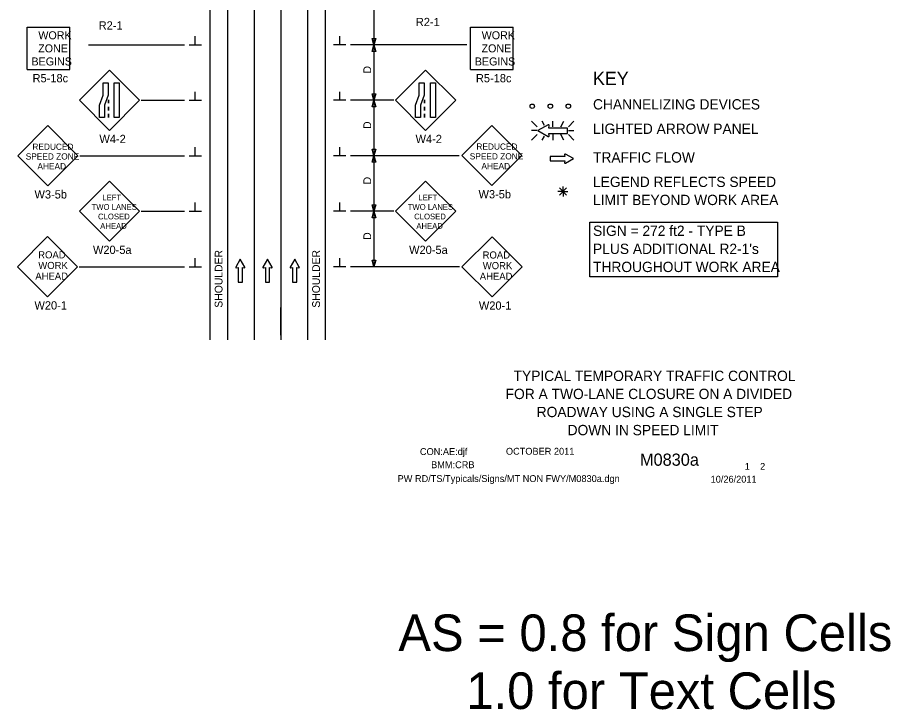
# Model space of a CAD drawing. Extents: x 16727 to 18475, y 5729 to 6909.
# Drawn here: x 16728 to 17515, y 5729 to 6353 of the extents above; entities that cross this region are included whole.
import ezdxf

# ---------------------------------------------------------------- set-up
doc = ezdxf.new("R2010")
doc.units = 0
for name, color, linetype in [('ALI_LEGAL_EX', 7, 'Continuous'), ('BORDER', 7, 'Continuous'), ('BORDER_SIGNAL_WO', 7, 'Continuous'), ('MT_SCRATCH_LEVEL_E', 7, 'Continuous'), ('PAVT_EDGE_EX', 7, 'Continuous'), ('TRAFFIC_SIGNS_PR', 7, 'Continuous'), ('TYPICAL_TEXT_DIMEN_EX', 7, 'Continuous'), ('TYPICAL_TEXT_DIMEN_PR', 7, 'Continuous')]:
    doc.layers.add(name, color=color, linetype=linetype)

msp = doc.modelspace()

# ---------------------------------------------------------------- linework, layer by layer
at = {"layer": 'ALI_LEGAL_EX'}
for p, q in [((16941.23, 6891.16), (16941.23, 6061.98)), ((16965.23, 6891.16), (16965.23, 6061.98)), ((16965.23, 6891.16), (16965.23, 6061.98))]:
    msp.add_line(p, q, dxfattribs=at)
for points in [[(16941.23, 6291.16), (16941.23, 6266.16)], [(16965.23, 6291.16), (16965.23, 6266.16)], [(16941.23, 6191.16), (16941.23, 6166.16)], [(16965.23, 6191.16), (16965.23, 6166.16)], [(16941.23, 6091.16), (16941.23, 6066.16)], [(16965.23, 6066.16), (16965.23, 6091.16)], [(16965.23, 6091.16), (16965.23, 6066.16)]]:
    msp.add_lwpolyline(points, dxfattribs=at)
at = {"layer": 'MT_SCRATCH_LEVEL_E'}
for p, q in [((17221.51, 6227.16), (17208.25, 6227.16)), ((17208.25, 6227.16), (17208.25, 6223.42)), ((17221.51, 6227.16), (17208.25, 6227.16)), ((17208.25, 6227.16), (17208.25, 6223.42)), ((17208.25, 6223.42), (17221.51, 6223.42)), ((17208.25, 6223.42), (17221.51, 6223.42)), ((17221.19, 6228.94), (17221.51, 6227.16)), ((17221.19, 6228.94), (17221.51, 6227.16)), ((17221.51, 6223.42), (17221.19, 6221.64)), ((17221.51, 6223.42), (17221.19, 6221.64)), ((17229.12, 6225.31), (17221.88, 6229.42)), ((17229.12, 6225.31), (17221.88, 6229.42)), ((17221.88, 6221.16), (17229.12, 6225.31)), ((17221.88, 6221.16), (17229.12, 6225.31)), ((16928.67, 6134.8), (16924.56, 6127.56)), ((16928.67, 6134.8), (16924.56, 6127.56)), ((16932.82, 6127.56), (16928.67, 6134.8)), ((16932.82, 6127.56), (16928.67, 6134.8)), ((16953.2, 6134.8), (16949.09, 6127.56)), ((16953.2, 6134.8), (16949.09, 6127.56)), ((16957.35, 6127.56), (16953.2, 6134.8)), ((16957.35, 6127.56), (16953.2, 6134.8)), ((16977.76, 6134.8), (16973.65, 6127.56)), ((16977.76, 6134.8), (16973.65, 6127.56)), ((16981.9, 6127.56), (16977.76, 6134.8)), ((16981.9, 6127.56), (16977.76, 6134.8)), ((16925.04, 6126.88), (16926.82, 6127.19)), ((16925.04, 6126.88), (16926.82, 6127.19)), ((16926.82, 6127.19), (16926.82, 6113.93)), ((16926.82, 6127.19), (16926.82, 6113.93)), ((16930.56, 6113.93), (16930.56, 6127.19)), ((16930.56, 6127.19), (16932.34, 6126.88)), ((16930.56, 6113.93), (16930.56, 6127.19)), ((16930.56, 6127.19), (16932.34, 6126.88)), ((16949.57, 6126.88), (16951.35, 6127.19)), ((16949.57, 6126.88), (16951.35, 6127.19)), ((16951.35, 6127.19), (16951.35, 6113.93)), ((16951.35, 6127.19), (16951.35, 6113.93)), ((16955.09, 6113.93), (16955.09, 6127.19)), ((16955.09, 6127.19), (16956.87, 6126.88)), ((16955.09, 6113.93), (16955.09, 6127.19)), ((16955.09, 6127.19), (16956.87, 6126.88)), ((16974.13, 6126.88), (16975.9, 6127.19)), ((16974.13, 6126.88), (16975.9, 6127.19)), ((16975.9, 6127.19), (16975.9, 6113.93)), ((16975.9, 6127.19), (16975.9, 6113.93)), ((16979.65, 6113.93), (16979.65, 6127.19)), ((16979.65, 6127.19), (16981.42, 6126.88)), ((16979.65, 6113.93), (16979.65, 6127.19)), ((16979.65, 6127.19), (16981.42, 6126.88)), ((16926.82, 6113.93), (16930.56, 6113.93)), ((16926.82, 6113.93), (16930.56, 6113.93)), ((16951.35, 6113.93), (16955.09, 6113.93)), ((16951.35, 6113.93), (16955.09, 6113.93)), ((16975.9, 6113.93), (16979.65, 6113.93)), ((16975.9, 6113.93), (16979.65, 6113.93))]:
    msp.add_line(p, q, dxfattribs=at)
for centre, start, end in [((17221.65, 6229.01), 60.42484, 189.96381), ((17221.65, 6229.01), 60.42484, 189.96381), ((17221.65, 6221.57), 170.03619, 299.77312), ((17221.65, 6221.57), 170.03619, 299.77312), ((16924.97, 6127.33), 150.42484, 279.96381), ((16924.97, 6127.33), 150.42484, 279.96381), ((16932.41, 6127.34), 260.03619, 29.77312), ((16932.41, 6127.34), 260.03619, 29.77312), ((16949.49, 6127.33), 150.42484, 279.96381), ((16949.49, 6127.33), 150.42484, 279.96381), ((16956.94, 6127.34), 260.03619, 29.77312), ((16956.94, 6127.34), 260.03619, 29.77312), ((16974.05, 6127.33), 150.42484, 279.96381), ((16974.05, 6127.33), 150.42484, 279.96381), ((16981.49, 6127.34), 260.03619, 29.77312), ((16981.49, 6127.34), 260.03619, 29.77312)]:
    msp.add_arc(centre, 0.463, start, end, dxfattribs=at)
at = {"layer": 'PAVT_EDGE_EX'}
for p, q in [((16901.23, 6891.16), (16901.23, 6061.98)), ((16917.23, 6891.16), (16917.23, 6061.98)), ((16917.23, 6891.16), (16917.23, 6061.98)), ((16989.23, 6891.16), (16989.23, 6061.98)), ((17005.23, 6891.16), (17005.23, 6061.98))]:
    msp.add_line(p, q, dxfattribs=at)
at = {"layer": 'TRAFFIC_SIGNS_PR'}
for p, q in [((16736.49, 6305.58), (16736.49, 6343.98)), ((16736.49, 6343.98), (16774.89, 6343.98)), ((16774.89, 6305.58), (16774.89, 6343.98)), ((17136.41, 6305.58), (17136.41, 6343.98)), ((17136.41, 6343.98), (17174.81, 6343.98)), ((17174.81, 6305.58), (17174.81, 6343.98)), ((16736.49, 6305.58), (16774.89, 6305.58)), ((16810.64, 6305.09), (16783.48, 6277.93)), ((16837.79, 6277.93), (16810.64, 6305.09)), ((17095.82, 6305.09), (17068.67, 6277.93)), ((17122.98, 6277.93), (17095.82, 6305.09)), ((17136.41, 6305.58), (17174.81, 6305.58)), ((16783.48, 6277.93), (16810.64, 6250.78)), ((16809.39, 6278.43), (16809.39, 6275.23)), ((16809.79, 6278.43), (16809.79, 6275.23)), ((16810.64, 6250.78), (16837.79, 6277.93)), ((17068.67, 6277.93), (17095.82, 6250.78)), ((17094.58, 6278.43), (17094.58, 6275.23)), ((17094.98, 6278.43), (17094.98, 6275.23)), ((17095.82, 6250.78), (17122.98, 6277.93)), ((16809.39, 6272.03), (16809.39, 6268.83)), ((16809.79, 6272.03), (16809.79, 6268.83)), ((17094.58, 6272.03), (17094.58, 6268.83)), ((17094.98, 6272.03), (17094.98, 6268.83)), ((16809.39, 6265.63), (16809.39, 6262.43)), ((16809.79, 6265.63), (16809.79, 6262.43)), ((17094.58, 6265.63), (17094.58, 6262.43)), ((17094.98, 6265.63), (17094.98, 6262.43)), ((16755.08, 6255.12), (16727.92, 6227.97)), ((16782.23, 6227.97), (16755.08, 6255.12)), ((17155.62, 6255.25), (17128.47, 6228.1)), ((17182.77, 6228.1), (17155.62, 6255.25)), ((17191.46, 6259.03), (17196.39, 6254.1)), ((17203.22, 6255.21), (17201.01, 6259.03)), ((17210.54, 6254.1), (17210.54, 6259.03)), ((17217.78, 6254.1), (17220.62, 6259.03)), ((17224.69, 6254.1), (17229.63, 6259.04)), ((17196.39, 6250.54), (17191.46, 6250.54)), ((17191.46, 6242.06), (17196.39, 6246.99)), ((17200.97, 6242.05), (17203.08, 6245.72)), ((17210.54, 6246.99), (17210.54, 6242.05)), ((17220.67, 6242.05), (17217.82, 6246.99)), ((17224.69, 6250.54), (17229.63, 6250.54)), ((17224.69, 6246.99), (17229.63, 6242.05)), ((16727.92, 6227.97), (16755.08, 6200.81)), ((16755.08, 6200.81), (16782.23, 6227.97)), ((17128.47, 6228.1), (17155.62, 6200.94)), ((17155.62, 6200.94), (17182.77, 6228.1)), ((16810.64, 6205.1), (16783.48, 6177.95)), ((16837.79, 6177.95), (16810.64, 6205.1)), ((17095.82, 6205.1), (17068.67, 6177.95)), ((17122.98, 6177.95), (17095.82, 6205.1)), ((16783.48, 6177.95), (16810.64, 6150.8)), ((16810.64, 6150.8), (16837.79, 6177.95)), ((17068.67, 6177.95), (17095.82, 6150.8)), ((17095.82, 6150.8), (17122.98, 6177.95)), ((16754.82, 6155.02), (16727.66, 6127.86)), ((16781.97, 6127.86), (16754.82, 6155.02)), ((17155.73, 6154.86), (17128.57, 6127.71)), ((17182.88, 6127.71), (17155.73, 6154.86)), ((16727.66, 6127.86), (16754.82, 6100.71)), ((16754.82, 6100.71), (16781.97, 6127.86)), ((17128.57, 6127.71), (17155.73, 6100.55)), ((17155.73, 6100.55), (17182.88, 6127.71))]:
    msp.add_line(p, q, dxfattribs=at)
for points in [[(16809.39, 6293.67), (16809.39, 6282.49), (16806.04, 6273.61), (16806.04, 6262.43), (16801.55, 6262.43), (16801.55, 6273.61), (16804.9, 6282.49), (16804.9, 6293.67)], [(16819.52, 6293.67), (16819.52, 6262.43), (16815.03, 6262.43), (16815.03, 6293.67)], [(17094.58, 6293.67), (17094.58, 6282.49), (17091.23, 6273.61), (17091.23, 6262.43), (17086.74, 6262.43), (17086.74, 6273.61), (17090.08, 6282.49), (17090.08, 6293.67)], [(17104.71, 6293.67), (17104.71, 6262.43), (17100.22, 6262.43), (17100.22, 6293.67)]]:
    msp.add_lwpolyline(points, close=True, dxfattribs=at)
for points in [[(17206.47, 6255.82), (17197.18, 6250.54), (17206.47, 6245.22)], [(17207.34, 6245.85), (17206.94, 6248.12), (17223.96, 6248.12), (17223.96, 6252.92), (17206.94, 6252.92), (17207.35, 6255.2)]]:
    msp.add_lwpolyline(points, dxfattribs=at)
for centre in [(17192.02, 6272.58), (17208.32, 6272.58), (17224.62, 6272.58)]:
    msp.add_circle(centre, 2, dxfattribs=at)
for centre, radius, start, end in [((17206.76, 6255.3), 0.598, 350.73078, 118.89165), ((17206.76, 6245.75), 0.597, 241.48329, 9.95933)]:
    msp.add_arc(centre, radius, start, end, dxfattribs=at)
at = {"layer": 'TYPICAL_TEXT_DIMEN_EX'}
msp.add_lwpolyline([(17243.85, 6168.04), (17413.3, 6168.04), (17413.3, 6118.85), (17243.85, 6118.85)], close=True, dxfattribs=at)
at = {"layer": 'TYPICAL_TEXT_DIMEN_PR'}
for p, q in [((17049.23, 6377.89), (17049.23, 6327.89)), ((16888.1, 6327.89), (16888.1, 6335.67)), ((17018.35, 6327.89), (17018.35, 6335.67)), ((17049.23, 6327.89), (17047.66, 6333.75)), ((17047.66, 6333.75), (17049.23, 6333.75)), ((17049.23, 6333.75), (17050.8, 6333.75)), ((17050.8, 6333.75), (17049.23, 6327.89)), ((16791.88, 6327.89), (16878.23, 6327.89)), ((16882.48, 6327.89), (16893.73, 6327.89)), ((17023.98, 6327.89), (17012.73, 6327.89)), ((17132.92, 6327.89), (17028.23, 6327.89)), ((17047.66, 6322.03), (17049.23, 6327.89)), ((17049.23, 6327.89), (17050.8, 6322.03)), ((17049.23, 6327.89), (17049.23, 6277.89)), ((17049.23, 6322.03), (17047.66, 6322.03)), ((17050.8, 6322.03), (17049.23, 6322.03)), ((16888.1, 6277.89), (16888.1, 6285.67)), ((17018.35, 6277.89), (17018.35, 6285.67)), ((16839.23, 6277.89), (16878.23, 6277.89)), ((16882.48, 6277.89), (16893.73, 6277.89)), ((17023.98, 6277.89), (17012.73, 6277.89)), ((17067.23, 6277.89), (17028.23, 6277.89)), ((17049.23, 6277.89), (17047.66, 6283.75)), ((17047.66, 6283.75), (17049.23, 6283.75)), ((17047.66, 6272.03), (17049.23, 6277.89)), ((17049.23, 6283.75), (17050.8, 6283.75)), ((17050.8, 6283.75), (17049.23, 6277.89)), ((17049.23, 6277.89), (17049.23, 6227.89)), ((17049.23, 6277.89), (17050.8, 6272.03)), ((17049.23, 6272.03), (17047.66, 6272.03)), ((17050.8, 6272.03), (17049.23, 6272.03)), ((16888.1, 6227.89), (16888.1, 6235.67)), ((17018.35, 6227.89), (17018.35, 6235.67)), ((17049.23, 6227.89), (17047.66, 6233.75)), ((17047.66, 6233.75), (17049.23, 6233.75)), ((17049.23, 6233.75), (17050.8, 6233.75)), ((17050.8, 6233.75), (17049.23, 6227.89)), ((16784.06, 6227.89), (16878.23, 6227.89)), ((16882.48, 6227.89), (16893.73, 6227.89)), ((17023.98, 6227.89), (17012.73, 6227.89)), ((17126.25, 6227.89), (17028.23, 6227.89)), ((17047.66, 6222.03), (17049.23, 6227.89)), ((17049.23, 6222.03), (17047.66, 6222.03)), ((17049.23, 6227.89), (17049.23, 6177.89)), ((17049.23, 6227.89), (17050.8, 6222.03)), ((17050.8, 6222.03), (17049.23, 6222.03)), ((17216.61, 6198.89), (17222.99, 6192.52)), ((17222.99, 6198.89), (17216.61, 6192.52)), ((17219.8, 6195.7), (17219.8, 6200.16)), ((17219.8, 6195.7), (17215.26, 6195.7)), ((17219.8, 6195.7), (17222.99, 6195.7)), ((17219.8, 6195.7), (17224.28, 6195.7)), ((17219.8, 6195.7), (17219.8, 6191.2)), ((16888.1, 6177.89), (16888.1, 6185.67)), ((17018.35, 6177.89), (17018.35, 6185.67)), ((17049.23, 6177.89), (17047.66, 6183.75)), ((17047.66, 6183.75), (17049.23, 6183.75)), ((17049.23, 6183.75), (17050.8, 6183.75)), ((17050.8, 6183.75), (17049.23, 6177.89)), ((16839.23, 6177.89), (16878.23, 6177.89)), ((16882.48, 6177.89), (16893.73, 6177.89)), ((17023.98, 6177.89), (17012.73, 6177.89)), ((17067.23, 6177.89), (17028.23, 6177.89)), ((17047.66, 6172.03), (17049.23, 6177.89)), ((17049.23, 6177.89), (17049.23, 6127.89)), ((17049.23, 6177.89), (17050.8, 6172.03)), ((17049.23, 6172.03), (17047.66, 6172.03)), ((17050.8, 6172.03), (17049.23, 6172.03)), ((16888.1, 6127.89), (16888.1, 6135.67)), ((17018.35, 6127.89), (17018.35, 6135.67)), ((16783.29, 6127.89), (16878.23, 6127.89)), ((16882.48, 6127.89), (16893.73, 6127.89)), ((17023.98, 6127.89), (17012.73, 6127.89)), ((17126.29, 6127.89), (17028.23, 6127.89)), ((17049.23, 6127.89), (17047.66, 6133.75)), ((17047.66, 6133.75), (17049.23, 6133.75)), ((17049.23, 6133.75), (17050.8, 6133.75)), ((17050.8, 6133.75), (17049.23, 6127.89))]:
    msp.add_line(p, q, dxfattribs=at)

# ---------------------------------------------------------------- texts
at = {"layer": 'BORDER'}
for s, p in [('TYPICAL TEMPORARY TRAFFIC CONTROL', (17175.21, 6024.8)), ('FOR A TWO-LANE CLOSURE ON A DIVIDED', (17168.02, 6008.5)), ('ROADWAY USING A SINGLE STEP', (17196.04, 5992.2)), ('DOWN IN SPEED LIMIT', (17223.92, 5975.9))]:
    msp.add_text(s, height=9.3, dxfattribs=at).set_placement(p)
at = {"layer": 'BORDER_SIGNAL_WO'}
for s, height, p in [('CON:AE:djf', 6.2, (17090.69, 5958.06)), ('    OCTOBER 2011    ', 6.2, (17159.08, 5958.34)), ('    M0830a   ', 11, (17272.86, 5948.38)), ('BMM:CRB   ', 6.2, (17100.81, 5946.17)), (' 1    2 ', 6.2, (17381.45, 5944.7)), ('PW RD/TS/Typicals/Signs/MT NON FWY/M0830a.dgn    ', 6.2, (17070.55, 5933.71)), ('10/26/2011    ', 6.2, (17352.93, 5933.13)), ('AS = 0.8 for Sign Cells', 33.0301, (17071.24, 5781.25)), ('     1.0 for Text Cells', 33.0301, (17071.24, 5729.02))]:
    msp.add_text(s, height=height, dxfattribs=at).set_placement(p)
at = {"layer": 'TRAFFIC_SIGNS_PR'}
for s, height, p in [('R2-1', 7.44, (16800.94, 6341.71)), ('R2-1', 7.44, (17087.02, 6344.79)), ('WORK', 7.217, (16746.49, 6332.95)), ('WORK', 7.217, (17146.41, 6332.95)), ('ZONE', 7.217, (16746.37, 6321.14)), ('ZONE', 7.217, (17146.29, 6321.14)), ('BEGINS', 7.217, (16740.3, 6309.33)), ('BEGINS', 7.217, (17140.22, 6309.33)), ('R5-18c', 7.44, (16741.3, 6294.14)), ('R5-18c', 7.44, (17141.22, 6294.14)), ('W4-2', 7.44, (16801.59, 6239.34)), ('W4-2', 7.44, (17086.78, 6239.34)), ('REDUCED', 5.6, (16741.13, 6233.27)), ('REDUCED', 5.6, (17141.68, 6233.4)), ('SPEED ZONE', 5.6, (16735.13, 6224.47)), ('SPEED ZONE', 5.6, (17135.67, 6224.6)), ('AHEAD', 5.6, (16745.69, 6215.67)), ('AHEAD', 5.6, (17146.23, 6215.8)), ('W3-5b', 7.44, (16743.03, 6189.37)), ('LEFT', 5.2, (16804.17, 6187.74)), ('LEFT', 5.2, (17089.36, 6187.74)), ('W3-5b', 7.44, (17143.57, 6189.5)), ('TWO LANES', 5.2, (16794.5, 6179.14)), ('TWO LANES', 5.2, (17079.68, 6179.14)), ('CLOSED', 5.2, (16800.35, 6170.54)), ('CLOSED', 5.2, (17085.53, 6170.54)), ('AHEAD', 5.2, (16802.29, 6161.94)), ('AHEAD', 5.2, (17087.48, 6161.94)), ('W20-5a', 7.44, (16795.78, 6139.36)), ('W20-5a', 7.44, (17080.96, 6139.36)), ('ROAD', 6.4, (16746.36, 6135.4)), ('ROAD', 6.4, (17147.27, 6135.24)), ('WORK', 6.4, (16746.47, 6125.8)), ('WORK', 6.4, (17147.38, 6125.64)), ('AHEAD', 6.4, (16743.78, 6116.2)), ('AHEAD', 6.4, (17144.69, 6116.04)), ('W20-1', 7.44, (16742.99, 6089.27)), ('W20-1', 7.44, (17143.9, 6089.11))]:
    msp.add_text(s, height=height, dxfattribs=at).set_placement(p)
at = {"layer": 'TYPICAL_TEXT_DIMEN_EX'}
for s, height, p in [('KEY', 12, (17246.86, 6291.68)), ('CHANNELIZING DEVICES', 9.3, (17246.86, 6269.63)), ('LIGHTED ARROW PANEL', 9.3, (17246.86, 6247.58)), ('TRAFFIC FLOW', 9.3, (17246.86, 6221.78)), ('LEGEND REFLECTS SPEED', 9.3, (17246.86, 6199.73)), ('LIMIT BEYOND WORK AREA', 9.3, (17246.86, 6183.43)), ('SIGN = 272 ft2 - TYPE B', 9.3, (17246.86, 6155.63)), ("PLUS ADDITIONAL R2-1's", 9.3, (17246.86, 6139.33)), ('THROUGHOUT WORK AREA', 9.3, (17246.86, 6123.03))]:
    msp.add_text(s, height=height, dxfattribs=at).set_placement(p)
at = {"layer": 'TYPICAL_TEXT_DIMEN_PR'}
for s, p in [('D', (17046.67, 6302.11)), ('D', (17046.67, 6252.11)), ('D', (17046.67, 6202.11)), ('D', (17046.67, 6152.11)), ('SHOULDER', (16912.61, 6090.91)), ('SHOULDER', (17000.51, 6090.91))]:
    msp.add_text(s, height=7, rotation=90, dxfattribs=at).set_placement(p)

doc.saveas('drawing.dxf')
